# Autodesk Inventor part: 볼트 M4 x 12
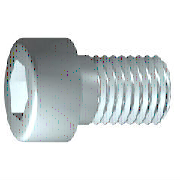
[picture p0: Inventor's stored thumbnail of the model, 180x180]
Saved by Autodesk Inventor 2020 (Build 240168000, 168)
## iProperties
Created: 2012-02
Part Number: 볼트 M4 x 12
Material: 강철, 연강
Description: 원통형 머리 캡 나사
Document SubType Name: Modeling
Standard: JIS B 1176
Designer: mdu-01
Standards Organization: JIS
Language: ko-KR
Size Designation: M4 x 12
Categories: <MemberInstance><Categories><Category DisplayName="조임쇠" InternalName="e4da775c-781d-43d5-af7c-5136215cf5a6" Mnemonic="FSTN"><Category DisplayName="볼트" InternalN
Density: 1 g/cm^3
Appearance: Steel
IsCustomPart: 1
Author: mdu-01
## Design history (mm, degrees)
sketch "스케치1"
  geometry: L1 (-1, 0)-(12, 0); L2 (12, 0)-(12, 2); L3 (12, 2)-(1.75, 2); L4 (1.75, 2)-(1.32, 2); L5 (1.32, 2)-(0, 2); L6 (0, 2)-(0, 3.5); L7 (0, 3.5)-(-4, 3.5); L8 (-4, 3.5)-(-4, 1.732); L9 (-4, 1.732)-(-2, 1.732); L10 (-2, 1.732)-(-1, 0); L11 (-7.2, 0)-(15.2, 0) reference; L12 (0, -0.7)-(0, 4.2) reference; L13 (1.75, 2)-(0, 2)
  constraints: 22 end point, 6 parallel, 2 collinear, 2 perpendicular, 1 horizontal, 1 point on line
  dimensions: "d1" = 10.25 distance from line of L3.end L2 (= GEL); "d2" = 0.42952 distance of L4.end L3.end (computed from GAL); "d3" = 4 distance between parallel lines of L8 L6 (= KOH); "d4" = 2 distance of L8.end L9.end (= INTI); "d5" = 60 deg angle of L10 L1; "d6" = 4 diameter of L3 L1 (= GD); "d7" = 4 diameter of L5 L1 (= BDM); "d8" = 3.4641 diameter of L9 L1 (= 1.1547 x SW); "d9" = 7 diameter of L7 L1 (= KOD); "d26" = 12 distance between parallel lines of L12 L2 (= NLG)
revolve "본체" sketch "스케치1" stored, may be unused: angle "d10" = 90 deg
sketch "스케치2"
  geometry: L1 (0, -4.9)-(0, 4.9) reference; L2 (-4.9, 0)-(4.9, 0) reference; L3 (1.732, 0)-(0.866, -1.5); L4 (0.866, -1.5)-(-0.866, -1.5); L5 (-0.866, -1.5)-(-1.732, 0); L6 (-1.732, 0)-(-0.866, 1.5); L7 (-0.866, 1.5)-(0.866, 1.5); L8 (0.866, 1.5)-(1.732, 0); 2 further points
  constraints: 12 end point, 1 coincident, 1 horizontal alignment, 1 point on line, 12 other
extrude "슬롯" join sketch "스케치2" stored distance "d11" = 10; taper "d12" = 0 deg
workplane "Work Plane1"
fillet "Fillet2" dims "d30" = 0.1 (= R)
body "Solid1"
fillet "모깎기1" dims "d17" = 0.4 (= RR)
feature "스레드" dims "d13" = 10.25 (= GEL), "d14" = 0
chamfer "모따기1" distance "d15" = 0.42941 (= -0.5 x SPD + 0.5 x GD); stored, may be unused: second distance "d16" = 0.42941 (= GUL), angle "d27" = 45 deg
other parameters: "GD" = 4 (= NND) [user parameter; used in 2 equation terms], "NLG" = 12 [user parameter; used in 1 equation term], "GEL" = 10.25 [user parameter; used in 2 equation terms], "KOD" = 7 [user parameter; used in 1 equation term], "KOH" = 4 [user parameter; used in 1 equation term], "INTI" = 2 [user parameter; used in 1 equation term], "GAL" = 0.42941 (= 0.61345 x PTC) [user parameter; used in 1 equation term], "GUL" = 0.42941 (= 0.61345 x PTC) [user parameter; used in 1 equation term], "BDM" = 4 (= NND) [user parameter; used in 1 equation term], "SW" = 3 [user parameter; used in 2 equation terms], "RR" = 0.4 [user parameter; used in 1 equation term], "SPD" = 3.14117 (= NND - 1.2269 x PTC) [user parameter; used in 1 equation term], "d19" = 0, "d28" = 0, "d29" = 0, "R" = 0.1 [user parameter; used in 1 equation term], "PHH" = 0.2 [user parameter], "GD1" = 3.14117 (= THREADDIA - 1.2269 x PTC) [user parameter], "THREADDIA" = 4 [user parameter; used in 1 equation term], "FAWI" = 45 deg [user parameter], "TPU" = 14.28571 (computed from PTC) [user parameter], "PTC" = 0.7 [user parameter; used in 5 equation terms], "NND" = 4 [user parameter; used in 3 equation terms], "TOA" = 30 deg [user parameter], "E0" = 3.465 (= 1.155 x SW) [user parameter]
